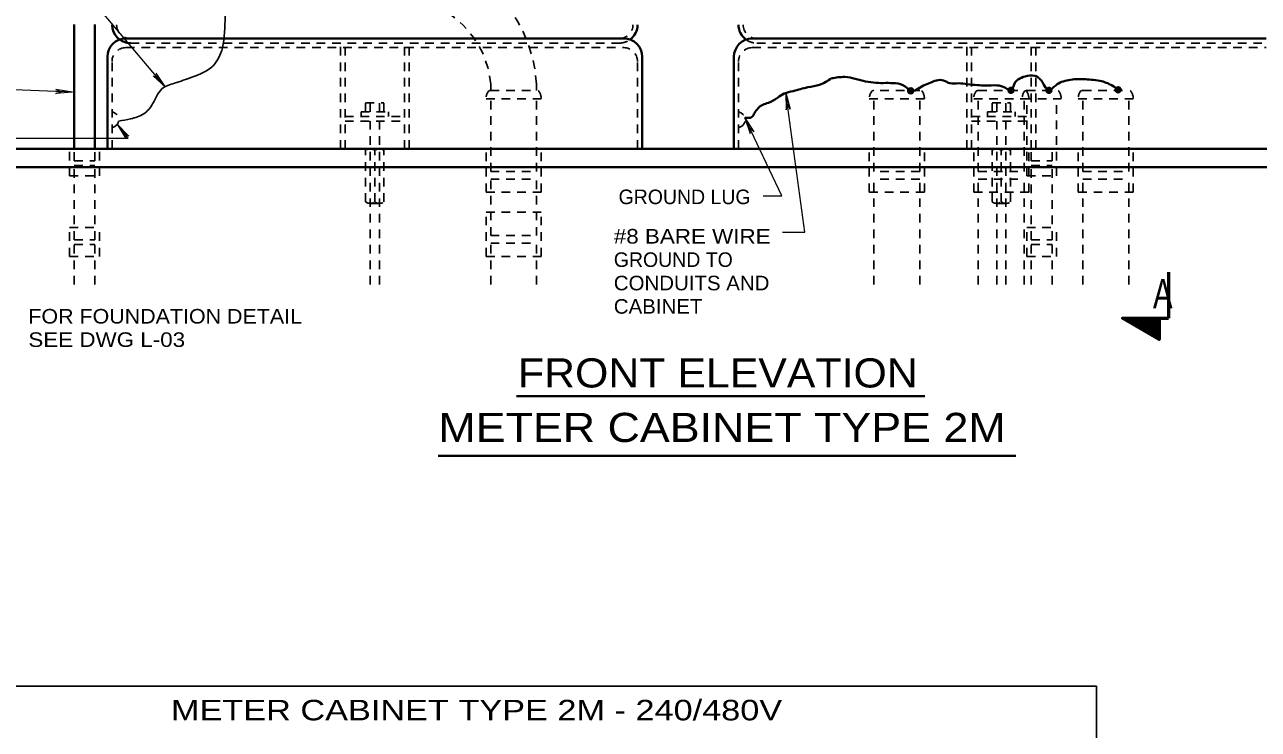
# Model space of a CAD drawing. Extents: x 312583 to 312854, y 144419 to 144597.
# Drawn here: x 312632.5 to 312696.9, y 144490.5 to 144527.3 of the extents above; entities that cross this region are included whole.
import ezdxf
from ezdxf.enums import TextEntityAlignment as Align

# ---------------------------------------------------------------- set-up
doc = ezdxf.new("R2010")
doc.units = 0
doc.header["$LTSCALE"] = 0.3
doc.linetypes.add('SHORT_DASHED', pattern=[2.7, 1.5, -1.2])
doc.layers.add('1', color=7, linetype='Continuous', lineweight=25)
doc.layers.add('2', color=7, linetype='Continuous', lineweight=13)

msp = doc.modelspace()

# ---------------------------------------------------------------- linework, layer by layer
at = {"layer": '1', "lineweight": 13}
msp.add_line((312639.8398, 144524.0303), (312628.9915, 144536.9563), dxfattribs=at)
at = {"layer": '1', "lineweight": 40}
for p, q in [((312635.0788, 144527.2963), (312635.0788, 144520.8256)), ((312636.1598, 144527.2963), (312636.1598, 144520.8256)), ((312637.7775, 144526.5756), (312663.7675, 144526.5756)), ((312670.4758, 144526.5756), (312697.3091, 144526.5756)), ((312636.8191, 144520.8256), (312636.8191, 144525.6173)), ((312664.7258, 144520.8256), (312664.7258, 144525.6173)), ((312669.5175, 144520.8256), (312669.5175, 144525.6173)), ((312630.5861, 144520.8256), (312703.4195, 144520.8256)), ((312629.6278, 144519.8673), (312704.3778, 144519.8673))]:
    msp.add_line(p, q, dxfattribs=at)
at = {"layer": '1', "linetype": 'SHORT_DASHED'}
for p, q in [((312638.0151, 144526.5756), (312663.5298, 144526.5756)), ((312638.0151, 144526.338), (312663.5298, 144526.338)), ((312648.9785, 144520.8256), (312648.9785, 144526.338)), ((312649.2161, 144520.8256), (312649.2161, 144526.338)), ((312652.3288, 144520.8256), (312652.3288, 144526.338)), ((312652.5665, 144520.8256), (312652.5665, 144526.338)), ((312670.7135, 144526.5756), (312697.0715, 144526.5756)), ((312670.7135, 144526.338), (312697.0715, 144526.338)), ((312681.6768, 144520.8256), (312681.6768, 144526.338)), ((312681.9145, 144520.8256), (312681.9145, 144526.338)), ((312685.0348, 144520.8256), (312685.0348, 144526.338)), ((312685.2725, 144520.8256), (312685.2725, 144526.338)), ((312637.7775, 144526.1003), (312663.7675, 144526.1003)), ((312670.4758, 144526.1003), (312697.3091, 144526.1003)), ((312637.0568, 144520.8256), (312637.0568, 144525.3796)), ((312664.4881, 144520.8256), (312664.4881, 144525.3796)), ((312669.7551, 144520.8256), (312669.7551, 144525.3796)), ((312656.8215, 144523.8693), (312656.8215, 144524.1913)), ((312659.2135, 144523.8693), (312659.2135, 144524.1913)), ((312656.8215, 144523.8693), (312659.2135, 144523.8693)), ((312679.2235, 144523.8693), (312676.8238, 144523.8693)), ((312682.2748, 144523.8693), (312684.6745, 144523.8693)), ((312684.8048, 144523.8693), (312686.3611, 144523.8693)), ((312687.7258, 144523.8693), (312690.1255, 144523.8693)), ((312650.5348, 144522.7423), (312650.5348, 144523.2253)), ((312651.0101, 144522.7423), (312651.0101, 144523.2253)), ((312651.2478, 144522.7423), (312651.2478, 144523.2253)), ((312656.5838, 144523.4323), (312659.4588, 144523.4323)), ((312656.8215, 144519.6373), (312656.8215, 144523.4323)), ((312659.2135, 144519.6373), (312659.2135, 144523.4323)), ((312679.4611, 144523.4323), (312676.5861, 144523.4323)), ((312676.8238, 144519.6373), (312676.8238, 144523.4323)), ((312679.2235, 144519.6373), (312679.2235, 144523.4323)), ((312682.0371, 144523.4323), (312684.9121, 144523.4323)), ((312682.2748, 144519.6373), (312682.2748, 144523.4323)), ((312683.2331, 144522.7423), (312683.2331, 144523.2253)), ((312683.7161, 144522.7423), (312683.7161, 144523.2253)), ((312683.9538, 144522.7423), (312683.9538, 144523.2253)), ((312684.5671, 144523.4323), (312686.5988, 144523.4323)), ((312684.6745, 144519.6373), (312684.6745, 144523.4323)), ((312684.8048, 144519.4073), (312684.8048, 144523.4323)), ((312686.3611, 144519.4073), (312686.3611, 144523.4323)), ((312687.4881, 144523.4323), (312690.3631, 144523.4323)), ((312687.7258, 144519.6373), (312687.7258, 144523.4323)), ((312690.1255, 144519.6373), (312690.1255, 144523.4323)), ((312649.2161, 144522.5046), (312652.3288, 144522.5046)), ((312649.2161, 144522.267), (312652.3288, 144522.267)), ((312650.0518, 144522.7423), (312651.4931, 144522.7423)), ((312650.0518, 144522.5046), (312650.0518, 144522.7423)), ((312650.5348, 144513.734), (312650.5348, 144522.267)), ((312651.0101, 144513.734), (312651.0101, 144522.267)), ((312651.4931, 144522.5046), (312651.4931, 144522.7423)), ((312681.9145, 144522.5046), (312685.0348, 144522.5046)), ((312681.9145, 144522.267), (312685.0348, 144522.267)), ((312682.7578, 144522.7423), (312684.1915, 144522.7423)), ((312682.7578, 144522.5046), (312682.7578, 144522.7423)), ((312683.2331, 144513.734), (312683.2331, 144522.267)), ((312683.7161, 144513.734), (312683.7161, 144522.267)), ((312684.1915, 144522.5046), (312684.1915, 144522.7423)), ((312634.8411, 144519.4073), (312634.8411, 144520.8256)), ((312635.0788, 144520.1893), (312635.0788, 144520.8256)), ((312636.1598, 144520.1893), (312636.1598, 144520.8256)), ((312636.3975, 144519.4073), (312636.3975, 144520.8256)), ((312650.2895, 144518.0503), (312650.2895, 144520.7413)), ((312650.7725, 144518.0503), (312650.7725, 144520.7413)), ((312651.2478, 144518.0503), (312651.2478, 144520.7413)), ((312656.5838, 144518.5563), (312656.5838, 144520.8256)), ((312659.4588, 144518.5563), (312659.4588, 144520.8256)), ((312676.5861, 144518.5563), (312676.5861, 144520.8256)), ((312679.4611, 144518.5563), (312679.4611, 144520.8256)), ((312682.0371, 144518.5563), (312682.0371, 144520.8256)), ((312682.9955, 144518.0503), (312682.9955, 144520.7413)), ((312683.4708, 144518.0503), (312683.4708, 144520.7413)), ((312683.9538, 144518.0503), (312683.9538, 144520.7413)), ((312684.9121, 144518.5563), (312684.9121, 144520.8256)), ((312685.0425, 144520.1893), (312685.0425, 144520.8256)), ((312686.1235, 144520.1893), (312686.1235, 144520.8256)), ((312687.4881, 144518.5563), (312687.4881, 144520.8256)), ((312690.3631, 144518.5563), (312690.3631, 144520.8256)), ((312635.0788, 144520.1893), (312636.1598, 144520.1893)), ((312635.0788, 144519.944), (312636.1598, 144519.944)), ((312635.0788, 144516.0723), (312635.0788, 144519.944)), ((312636.1598, 144516.0723), (312636.1598, 144519.944)), ((312685.0425, 144520.1893), (312686.1235, 144520.1893)), ((312685.0425, 144519.944), (312686.1235, 144519.944)), ((312685.0425, 144516.0723), (312685.0425, 144519.944)), ((312686.1235, 144516.0723), (312686.1235, 144519.944)), ((312634.8411, 144519.4073), (312636.3975, 144519.4073)), ((312656.8215, 144519.6373), (312659.2135, 144519.6373)), ((312656.8215, 144519.2386), (312659.2135, 144519.2386)), ((312656.8215, 144516.287), (312656.8215, 144519.2386)), ((312659.2135, 144516.287), (312659.2135, 144519.2386)), ((312679.2235, 144519.6373), (312676.8238, 144519.6373)), ((312679.2235, 144519.2386), (312676.8238, 144519.2386)), ((312676.8238, 144513.734), (312676.8238, 144519.2386)), ((312679.2235, 144513.734), (312679.2235, 144519.2386)), ((312682.2748, 144519.6373), (312684.6745, 144519.6373)), ((312682.2748, 144519.2386), (312684.6745, 144519.2386)), ((312682.2748, 144513.734), (312682.2748, 144519.2386)), ((312684.6745, 144513.734), (312684.6745, 144519.2386)), ((312684.8048, 144519.4073), (312686.3611, 144519.4073)), ((312687.7258, 144519.6373), (312690.1255, 144519.6373)), ((312687.7258, 144519.2386), (312690.1255, 144519.2386)), ((312687.7258, 144513.734), (312687.7258, 144519.2386)), ((312690.1255, 144513.734), (312690.1255, 144519.2386)), ((312656.5838, 144518.5563), (312659.4588, 144518.5563)), ((312679.4611, 144518.5563), (312676.5861, 144518.5563)), ((312682.0371, 144518.5563), (312684.9121, 144518.5563)), ((312687.4881, 144518.5563), (312690.3631, 144518.5563)), ((312651.0101, 144517.9736), (312650.5348, 144517.9736)), ((312683.7161, 144517.9736), (312683.2331, 144517.9736)), ((312656.5838, 144517.506), (312659.4588, 144517.506)), ((312656.5838, 144515.206), (312656.5838, 144517.506)), ((312659.4588, 144515.206), (312659.4588, 144517.506)), ((312634.8411, 144515.206), (312634.8411, 144516.7163)), ((312634.8411, 144516.7163), (312636.3975, 144516.7163)), ((312636.3975, 144515.206), (312636.3975, 144516.7163)), ((312684.8048, 144515.206), (312684.8048, 144516.7163)), ((312684.8048, 144516.7163), (312686.3611, 144516.7163)), ((312686.3611, 144515.206), (312686.3611, 144516.7163)), ((312635.0788, 144516.0723), (312636.1598, 144516.0723)), ((312635.0788, 144515.827), (312636.1598, 144515.827)), ((312635.0788, 144513.734), (312635.0788, 144515.827)), ((312636.1598, 144513.734), (312636.1598, 144515.827)), ((312656.8215, 144516.287), (312659.2135, 144516.287)), ((312656.8215, 144515.8883), (312659.2135, 144515.8883)), ((312656.8215, 144513.734), (312656.8215, 144515.8883)), ((312659.2135, 144513.734), (312659.2135, 144515.8883)), ((312685.0425, 144516.0723), (312686.1235, 144516.0723)), ((312685.0425, 144515.827), (312686.1235, 144515.827)), ((312685.0425, 144513.734), (312685.0425, 144515.827)), ((312686.1235, 144513.734), (312686.1235, 144515.827)), ((312634.8411, 144515.206), (312636.3975, 144515.206)), ((312656.5838, 144515.206), (312659.4588, 144515.206)), ((312684.8048, 144515.206), (312686.3611, 144515.206))]:
    msp.add_line(p, q, dxfattribs=at)
at = {"layer": '1', "lineweight": 53}
for p in [(312692.1955, 144514.378), (312691.7201, 144511.986)]:
    msp.add_line(p, (312692.1955, 144511.986), dxfattribs=at)
at = {"layer": '1', "lineweight": 35}
for p, q in [((312689.8188, 144511.986), (312689.8188, 144511.9706)), ((312689.8495, 144511.986), (312689.8418, 144511.963)), ((312689.8801, 144511.986), (312689.8571, 144511.9476)), ((312689.9031, 144511.986), (312689.8801, 144511.94)), ((312689.9338, 144511.986), (312689.9031, 144511.9246)), ((312689.9568, 144511.986), (312689.9185, 144511.917)), ((312689.9875, 144511.986), (312689.9415, 144511.9016)), ((312690.0181, 144511.986), (312689.9645, 144511.894)), ((312690.0488, 144511.986), (312689.9798, 144511.8786)), ((312690.0718, 144511.986), (312690.0028, 144511.871)), ((312690.0948, 144511.986), (312690.0258, 144511.8556)), ((312690.1255, 144511.986), (312690.0488, 144511.848)), ((312690.1485, 144511.986), (312690.0641, 144511.8326)), ((312690.1791, 144511.986), (312690.0871, 144511.8173)), ((312690.2098, 144511.986), (312690.1101, 144511.8096)), ((312690.2405, 144511.986), (312690.1255, 144511.7943)), ((312690.2635, 144511.986), (312690.1485, 144511.779)), ((312690.2941, 144511.986), (312690.1715, 144511.7713)), ((312690.3171, 144511.986), (312690.1868, 144511.756)), ((312690.3478, 144511.986), (312690.2098, 144511.7483)), ((312690.3785, 144511.986), (312690.2328, 144511.733)), ((312690.4015, 144511.986), (312690.2481, 144511.7253)), ((312690.4321, 144511.986), (312690.2788, 144511.71)), ((312690.4551, 144511.986), (312690.2941, 144511.7023)), ((312690.4858, 144511.986), (312690.3171, 144511.687)), ((312690.5165, 144511.986), (312690.3401, 144511.6793)), ((312690.5395, 144511.986), (312690.3555, 144511.664)), ((312690.5701, 144511.986), (312690.3785, 144511.6563)), ((312690.5931, 144511.986), (312690.4015, 144511.641)), ((312690.6238, 144511.986), (312690.4168, 144511.6256)), ((312690.6468, 144511.986), (312690.4398, 144511.618)), ((312690.6775, 144511.986), (312690.4628, 144511.6026)), ((312690.7081, 144511.986), (312690.4781, 144511.5873)), ((312690.7388, 144511.986), (312690.5011, 144511.5796)), ((312690.7618, 144511.986), (312690.5241, 144511.5643)), ((312690.7848, 144511.986), (312690.5471, 144511.5566)), ((312690.8155, 144511.986), (312690.5625, 144511.5413)), ((312690.8461, 144511.986), (312690.5855, 144511.5336)), ((312690.8691, 144511.986), (312690.6085, 144511.5183)), ((312690.8998, 144511.986), (312690.6238, 144511.5106)), ((312690.9305, 144511.986), (312690.6468, 144511.4953)), ((312690.9535, 144511.986), (312690.6698, 144511.4876)), ((312690.9841, 144511.986), (312690.6851, 144511.4723)), ((312691.0148, 144511.986), (312690.7081, 144511.4646)), ((312691.0378, 144511.986), (312690.7311, 144511.4493)), ((312691.0685, 144511.9783), (312690.7465, 144511.434)), ((312691.0915, 144511.986), (312690.7771, 144511.4263)), ((312691.1221, 144511.986), (312690.7925, 144511.411)), ((312691.1451, 144511.986), (312690.8155, 144511.4033)), ((312691.1758, 144511.986), (312690.8385, 144511.388)), ((312691.2065, 144511.986), (312690.8538, 144511.3803)), ((312691.2371, 144511.986), (312690.8768, 144511.365)), ((312691.2601, 144511.986), (312690.8998, 144511.3573)), ((312691.2831, 144511.986), (312690.9151, 144511.342)), ((312691.3138, 144511.9783), (312690.9381, 144511.3343)), ((312691.3445, 144511.986), (312690.9611, 144511.319)), ((312691.3675, 144511.986), (312690.9765, 144511.3113)), ((312691.3981, 144511.986), (312690.9995, 144511.296)), ((312691.4288, 144511.986), (312691.0225, 144511.2806)), ((312691.4518, 144511.986), (312691.0455, 144511.273)), ((312691.4825, 144511.986), (312691.0608, 144511.2576)), ((312691.5131, 144511.986), (312691.0838, 144511.2423)), ((312691.5361, 144511.9783), (312691.1068, 144511.2346)), ((312691.5668, 144511.9783), (312691.1221, 144511.2193)), ((312691.5898, 144511.986), (312691.1451, 144511.2116)), ((312691.6205, 144511.986), (312691.1681, 144511.1963)), ((312691.6435, 144511.986), (312691.1835, 144511.1886)), ((312691.6741, 144511.986), (312691.2065, 144511.1733)), ((312691.7048, 144511.986), (312691.2295, 144511.1656)), ((312691.7201, 144511.963), (312691.2448, 144511.1503)), ((312691.7201, 144511.9093), (312691.2755, 144511.1426)), ((312691.7201, 144511.871), (312691.2908, 144511.1273)), ((312691.7201, 144511.8173), (312691.3138, 144511.1196)), ((312691.7201, 144511.7713), (312691.3368, 144511.1043)), ((312691.7201, 144511.7253), (312691.3521, 144511.089)), ((312691.7201, 144511.6793), (312691.3751, 144511.0813)), ((312691.7201, 144511.6256), (312691.3981, 144511.066)), ((312691.7201, 144511.5796), (312691.4135, 144511.0506)), ((312691.7201, 144511.5336), (312691.4365, 144511.043)), ((312691.7201, 144511.48), (312691.4518, 144511.0276)), ((312691.7201, 144511.434), (312691.4748, 144511.02)), ((312691.7201, 144511.388), (312691.4978, 144511.0046)), ((312691.7201, 144511.3343), (312691.5131, 144510.997)), ((312691.7201, 144511.2883), (312691.5438, 144510.9816)), ((312691.7201, 144511.2423), (312691.5591, 144510.974)), ((312691.7201, 144511.1963), (312691.5821, 144510.9586)), ((312691.7201, 144511.1426), (312691.6051, 144510.951)), ((312691.7201, 144511.1043), (312691.6205, 144510.9356)), ((312691.7201, 144511.0506), (312691.6435, 144510.928)), ((312691.7201, 144511.0046), (312691.6665, 144510.9126)), ((312691.7201, 144510.951), (312691.6818, 144510.8973)), ((312691.7201, 144510.905), (312691.7048, 144510.8896))]:
    msp.add_line(p, q, dxfattribs=at)
at = {"layer": '1'}
for p, q in [((312622.9059, 144492.7843), (312688.4513, 144492.7843)), ((312688.4513, 144492.7843), (312688.4513, 144445.8337))]:
    msp.add_line(p, q, dxfattribs=at)
at = {"layer": '1', "linetype": 'SHORT_DASHED'}
for points in [[(312650.2895, 144522.7423), (312650.2895, 144523.2253), (312651.2478, 144523.2253)], [(312682.9955, 144522.7423), (312682.9955, 144523.2253), (312683.9538, 144523.2253)]]:
    msp.add_lwpolyline(points, dxfattribs=at)
at = {"layer": '1', "lineweight": 53}
msp.add_lwpolyline([(312691.7201, 144511.986), (312691.7201, 144510.8743), (312689.8035, 144511.986)], close=True, dxfattribs=at)
at = {"layer": '1', "lineweight": 40}
for centre, radius in [((312678.7443, 144523.8434), 0.1358), ((312678.7443, 144523.8434), 0.1174), ((312678.7443, 144523.8434), 0.1057), ((312678.7443, 144523.8434), 0.0822), ((312678.7443, 144523.8434), 0.0575), ((312678.7443, 144523.8434), 0.0403), ((312678.7443, 144523.8434), 0.0282), ((312678.7443, 144523.8434), 0.0197), ((312678.7443, 144523.8434), 0.0138), ((312683.9797, 144523.8674), 0.1358), ((312683.9797, 144523.8674), 0.1174), ((312683.9797, 144523.8674), 0.1057), ((312683.9797, 144523.8674), 0.0822), ((312683.9797, 144523.8674), 0.0575), ((312683.9797, 144523.8674), 0.0403), ((312683.9797, 144523.8674), 0.0282), ((312683.9797, 144523.8674), 0.0197), ((312683.9797, 144523.8674), 0.0138), ((312685.9577, 144523.8674), 0.1358), ((312685.9577, 144523.8674), 0.1174), ((312685.9577, 144523.8674), 0.1057), ((312685.9577, 144523.8674), 0.0822), ((312685.9577, 144523.8674), 0.0575), ((312685.9577, 144523.8674), 0.0403), ((312685.9577, 144523.8674), 0.0282), ((312685.9577, 144523.8674), 0.0197), ((312685.9577, 144523.8674), 0.0138), ((312689.5715, 144523.9), 0.1358), ((312689.5715, 144523.9), 0.1174), ((312689.5715, 144523.9), 0.1057), ((312689.5715, 144523.9), 0.0822), ((312689.5715, 144523.9), 0.0575), ((312689.5715, 144523.9), 0.0403), ((312689.5715, 144523.9), 0.0282), ((312689.5715, 144523.9), 0.0197), ((312689.5715, 144523.9), 0.0138)]:
    msp.add_circle(centre, radius, dxfattribs=at)
at = {"layer": '1', "linetype": 'SHORT_DASHED'}
for centre, radius, start, end in [((312651.9456, 144523.7862), 7.2781, 3.16058, 87.12347), ((312651.9456, 144523.7862), 4.8914, 4.70558, 85.88958), ((312638.0142, 144527.2944), 0.7188, 180, 270), ((312663.5288, 144527.2944), 0.7188, 270, 0), ((312670.7163, 144527.2944), 0.7188, 180, 270), ((312663.5288, 144527.2944), 0.9583, 270, 306.01567), ((312670.7163, 144527.2944), 0.9583, 233.98433, 270), ((312637.7746, 144525.3777), 0.7188, 90, 180), ((312663.7684, 144525.3777), 0.7188, 0, 90), ((312670.4768, 144525.3777), 0.7188, 90, 180), ((312636.9905, 144522.3336), 0.4076, 285.15764, 77.61644), ((312669.6926, 144522.3336), 0.4076, 285.15764, 77.61644), ((312650.5319, 144520.4379), 0.3858, 51.61151, 128.38849), ((312651.0111, 144520.4045), 0.4125, 54.49327, 125.50673), ((312683.2341, 144520.4379), 0.3858, 51.61151, 128.38849), ((312683.7133, 144520.4045), 0.4125, 54.49327, 125.50673), ((312650.5319, 144518.3823), 0.4125, 234.49327, 305.50673), ((312651.0111, 144518.3823), 0.4125, 234.49327, 305.50673), ((312683.2341, 144518.3823), 0.4125, 234.49327, 305.50673), ((312683.7133, 144518.3823), 0.4125, 234.49327, 305.50673)]:
    msp.add_arc(centre, radius, start, end, dxfattribs=at)
at = {"layer": '1', "lineweight": 40}
for centre, start, end in [((312638.0142, 144527.2944), 180, 270), ((312663.5288, 144527.2944), 306.01567, 0), ((312670.7163, 144527.2944), 180, 233.98433), ((312637.7746, 144525.6173), 90, 180), ((312663.7684, 144525.6173), 0, 90), ((312670.4768, 144525.6173), 90, 180)]:
    msp.add_arc(centre, 0.9583, start, end, dxfattribs=at)
at = {"layer": '1', "linetype": 'SHORT_DASHED'}
for centre, major_axis, start_param, end_param in [((312656.8205, 144523.4352), (0, -0.4351), 3.1415927, 4.712389), ((312659.2163, 144523.4352), (0, 0.4351), 4.712389, 6.2831853), ((312676.8257, 144523.4352), (0, -0.4351), 3.1415927, 4.712389), ((312679.2216, 144523.4352), (0, 0.4351), 4.712389, 6.2831853), ((312682.2758, 144523.4352), (0, -0.4351), 3.1415927, 4.712389), ((312684.8029, 144523.4352), (0, -0.4351), 3.1415927, 4.712389), ((312684.6716, 144523.4352), (0, 0.4351), 4.712389, 6.2831853), ((312686.3602, 144523.4352), (0, 0.4351), 4.712389, 6.2831853), ((312687.7258, 144523.4352), (0, -0.4351), 3.1415927, 4.712389), ((312690.1216, 144523.4352), (0, 0.4351), 4.712389, 6.2831853)]:
    msp.add_ellipse(centre, major_axis=major_axis, ratio=0.550661, start_param=start_param, end_param=end_param, dxfattribs=at)
at = {"layer": '1'}
msp.add_spline([(312637.3941, 144522.2593), (312638.0228, 144522.382), (312638.7205, 144522.6503), (312639.1728, 144523.164), (312639.6558, 144523.946), (312640.3151, 144524.245), (312641.2198, 144524.5516), (312642.3315, 144525.1496), (312642.8145, 144526.085), (312642.9678, 144527.718), (312643.3358, 144530.4396)], degree=3, dxfattribs=at)
at = {"layer": '1', "lineweight": 40}
for points in [[(312674.6158, 144524.498), (312673.9871, 144524.1606), (312673.3738, 144524.0303), (312672.6148, 144523.831), (312672.1395, 144523.7006), (312671.7945, 144523.486), (312671.3191, 144523.2176), (312671.0201, 144523.118), (312670.5908, 144522.6733), (312670.4605, 144522.4816), (312670.0848, 144522.4433)], [(312689.5735, 144523.9), (312689.2668, 144524.1146), (312688.6151, 144524.3676), (312688.1781, 144524.4213), (312687.3808, 144524.452), (312686.6218, 144524.3063), (312686.3151, 144524.13), (312685.9548, 144523.8693), (312685.6175, 144524.291), (312685.4718, 144524.4826), (312685.2265, 144524.6283), (312684.7128, 144524.5976), (312684.3525, 144524.4366), (312684.2068, 144524.291), (312683.9768, 144523.8693), (312683.6855, 144523.9996), (312683.2485, 144524.13), (312682.6505, 144524.1146), (312682.2288, 144524.1453), (312681.6921, 144524.1913), (312681.2551, 144524.2373), (312680.7875, 144524.2373), (312680.4655, 144524.383), (312680.0898, 144524.383), (312679.7678, 144524.2603), (312679.4075, 144524.1146), (312678.7481, 144523.8463), (312678.4568, 144524.0763), (312677.9508, 144524.2373), (312676.9311, 144524.2603), (312676.3945, 144524.337), (312675.3058, 144524.567), (312674.6158, 144524.498)]]:
    msp.add_spline(points, degree=3, dxfattribs=at)
at = {"layer": '2'}
for p, q in [((312639.1958, 144524.6283), (312639.4565, 144524.4826)), ((312639.8398, 144524.0303), (312639.1958, 144524.6283)), ((312639.3645, 144524.7663), (312639.4565, 144524.4826)), ((312639.8398, 144524.0303), (312639.3645, 144524.7663)), ((312634.9868, 144523.7773), (312629.2291, 144524.0073)), ((312634.1205, 144523.7006), (312634.3965, 144523.7926)), ((312634.9868, 144523.7773), (312634.1205, 144523.7006)), ((312634.1281, 144523.9153), (312634.3965, 144523.7926)), ((312634.9868, 144523.7773), (312634.1281, 144523.9153)), ((312673.2128, 144516.4633), (312672.2315, 144523.7313)), ((312672.2315, 144523.7313), (312672.2468, 144522.8573)), ((312672.2315, 144523.7313), (312672.4538, 144522.888)), ((312672.2468, 144522.8573), (312672.3158, 144523.1486)), ((312672.4538, 144522.888), (312672.3158, 144523.1486)), ((312672.0168, 144518.3723), (312670.0848, 144522.4433)), ((312670.0848, 144522.4433), (312670.3608, 144521.6153)), ((312670.0848, 144522.4433), (312670.5525, 144521.7073)), ((312637.3175, 144522.0983), (312637.9385, 144521.485)), ((312637.3175, 144522.0983), (312637.7698, 144521.3546)), ((312637.9385, 144521.485), (312637.6855, 144521.6383)), ((312637.7698, 144521.3546), (312637.6855, 144521.6383)), ((312670.3608, 144521.6153), (312670.3378, 144521.9066)), ((312670.5525, 144521.7073), (312670.3378, 144521.9066)), ((312671.0431, 144518.3723), (312672.0168, 144518.3723)), ((312672.0475, 144516.4633), (312673.2128, 144516.4633))]:
    msp.add_line(p, q, dxfattribs=at)
at = {"layer": '2', "lineweight": 40}
for p, q in [((312658.1603, 144507.9072), (312679.4755, 144507.9072)), ((312654.0859, 144504.8059), (312684.236, 144504.8059))]:
    msp.add_line(p, q, dxfattribs=at)
at = {"layer": '2'}
msp.add_lwpolyline([(312629.3671, 144521.3776), (312637.8925, 144521.37), (312637.3175, 144522.0983)], dxfattribs=at)

# ---------------------------------------------------------------- texts
at = {"layer": '1', "width": 0.75}
msp.add_text('A', height=1.533, dxfattribs=at).set_placement((312691.9041, 144512.492), align=Align.CENTER)
at = {"layer": '2'}
for s, p in [('GROUND LUG', (312663.4978, 144517.9313)), ('GROUND TO', (312663.2481, 144514.655))]:
    msp.add_text(s, height=0.76, dxfattribs=at).set_placement(p)
for s, width, p in [('#8 BARE WIRE', 1.15, (312663.2481, 144515.875)), ('CONDUITS AND', 1.05, (312663.2481, 144513.435)), ('CABINET', 1.05, (312663.2481, 144512.215)), ('FOR FOUNDATION DETAIL', 1.1, (312632.6868, 144511.7013)), ('SEE DWG L-03', 1.15, (312632.6868, 144510.4813))]:
    msp.add_text(s, height=0.76, dxfattribs=dict(at, width=width)).set_placement(p)
for s, height, width, p in [('FRONT ELEVATION', 1.52, 1.1, (312668.6776, 144508.365)), ('METER CABINET TYPE 2M', 1.52, 1.15, (312668.8963, 144505.5208)), ('METER CABINET TYPE 2M - 240/480V', 1.07, 1.25, (312656.0836, 144490.9961))]:
    msp.add_text(s, height=height, dxfattribs=dict(at, width=width)).set_placement(p, align=Align.CENTER)

doc.saveas('drawing.dxf')
